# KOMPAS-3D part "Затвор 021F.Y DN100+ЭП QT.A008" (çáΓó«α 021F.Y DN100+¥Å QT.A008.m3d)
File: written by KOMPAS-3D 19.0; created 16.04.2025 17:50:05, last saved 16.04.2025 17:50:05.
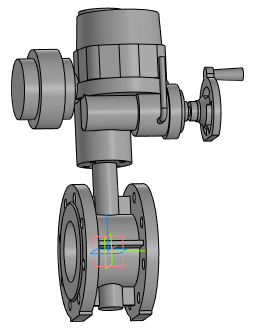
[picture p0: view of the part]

Document properties: Полное имя файла: Затвор 021F.Y DN100+ЭП QT.A008.a3d

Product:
- Part/product: Затвор 021F.Y DN100+ЭП QT.A008
    Масса: 50.7961

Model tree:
1. Операция без истории:1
